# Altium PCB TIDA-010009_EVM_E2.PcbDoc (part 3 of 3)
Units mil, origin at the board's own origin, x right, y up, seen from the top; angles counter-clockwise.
Board outline 4485 x 3050 mil, 4 copper layers (Top Layer, Signal Layer 1, Signal Layer 2, Bottom Layer), stack 61.634 mil thick; 216 components, 95 nets, 514 pads, 224 vias.
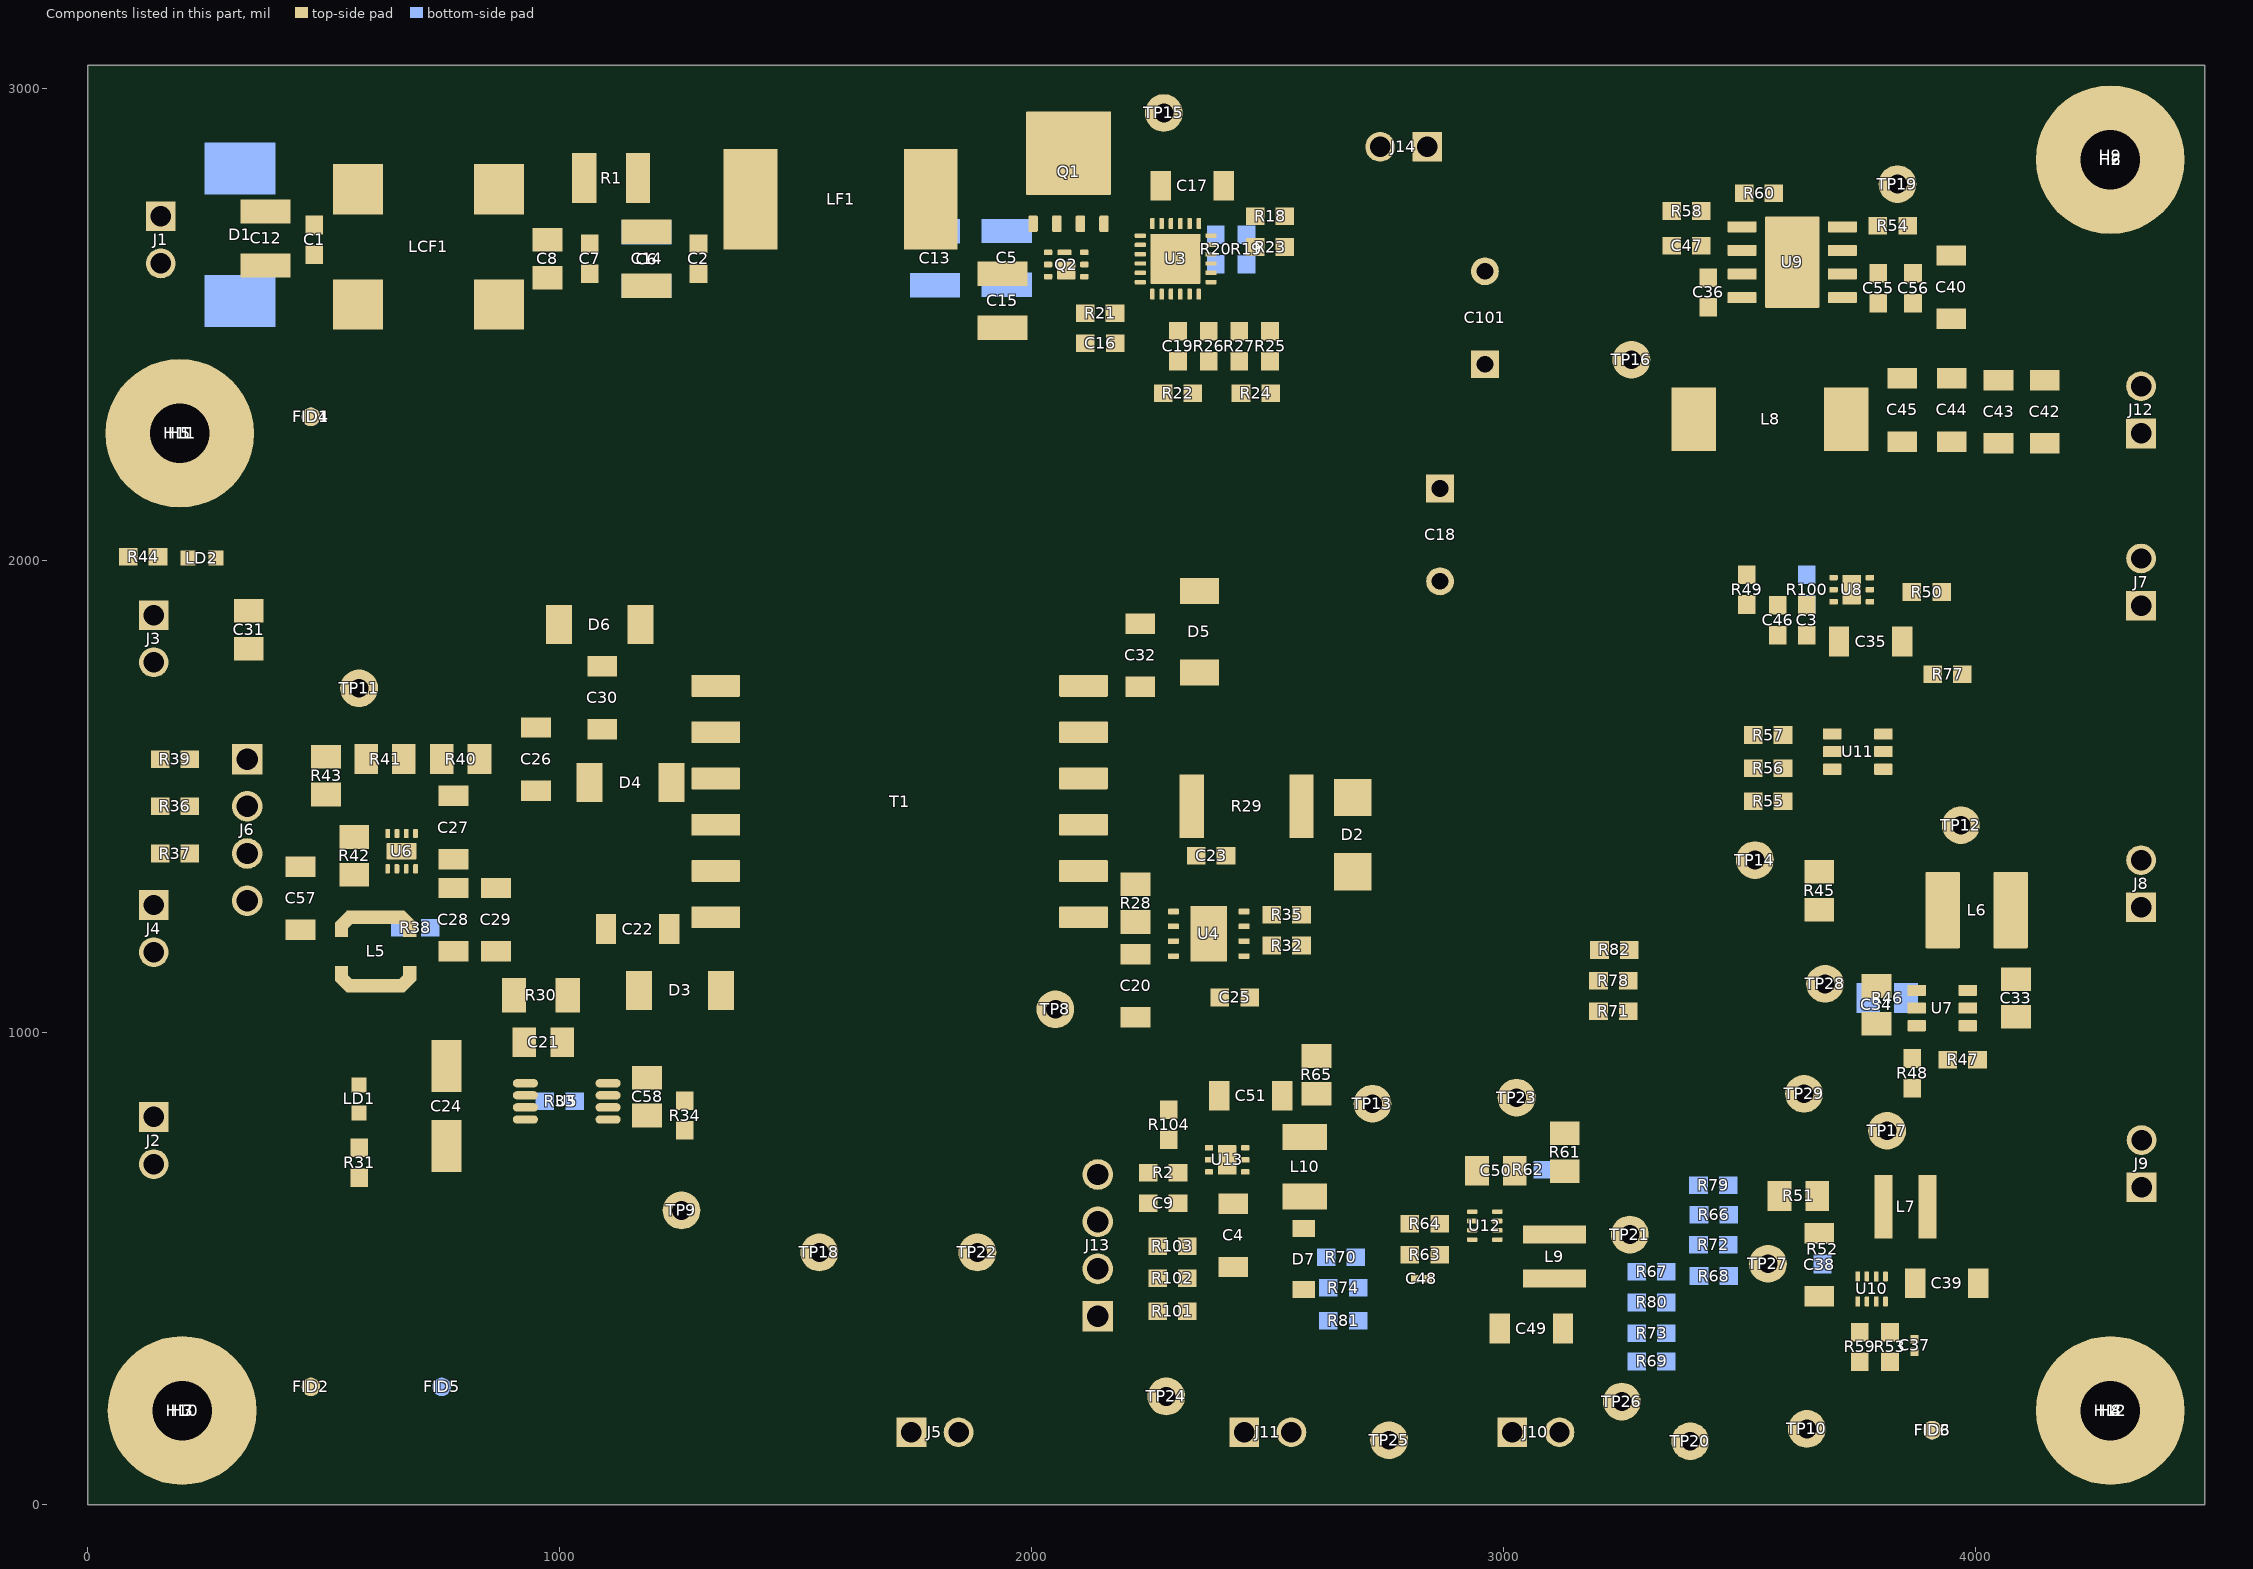
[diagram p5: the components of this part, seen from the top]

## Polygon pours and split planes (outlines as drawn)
GND on Top Layer "Top Layer-No Net" (solid, remove dead copper, pour order 122): 2535,1985 2535,1565 2160,1190 2160,90 2210,40 4415,40 4459.51,84.51 4459.51,2974.51 4465,2980 4425,3020 40,3020 20,3000 20,2510 165,2365 1780,2365 2155,2365
2.5V/1A on Top Layer "2.5V/1A_L01_P020" (solid, remove dead copper, pour order 20): 3038,500.49 3038,463 3090,411 3090,193 3078,181 3078,133.8 3114.3,97.5 3141.5,97.5 3174,130 3174,498.57 3168,504.57 3042.08,504.57
1.2V/1A on Top Layer "1.2V/1A_L01_P078" (solid, remove dead copper, pour order 78): 3977,438.88 3989.88,426 4114,426 4126,436 4252,562 4365,562 4392,589 4392,697 4385,704 4243.83,704 4078.83,539 4033,539 3988,584 3988,666.19 3934,720.19 3879.54,720.19 3873.5,714.16 3873.5,564.06 3884.56,553 3933.73,553 3977,509.73
EFUSE_OUT on Top Layer "Top Layer-No Net" (solid, remove dead copper, pour order 94): 2349.76,2929.76 2349.76,2993 2878,2993 2878,2729 2880,2727 2862.76,2709.76 2504.76,2709.76 2504,2710.53 2504,2848 2360,2848 2349.76,2858.24
GND on Top Layer "Top Layer-No Net" (solid, remove dead copper, pour order 124): 985,1400 1065,1400 1100,1435 1170,1435 1170,1417 1048,1295 985,1295
3.3V/2A on Top Layer "Top Layer-No Net" (solid, remove dead copper, pour order 108): 4290.32,1302 4158.32,1170 4134.82,1170 4121.29,1183.53 4121.29,1353.71 4108,1367 4040,1367 4018,1345 4018,1124.73 4065.73,1077 4233,1077 4382,1226 4395,1239 4395,1291 4384,1302
EFUSE_OUT on Top Layer "TOP_LAYER_EFUSE_OUT_P104" (solid, remove dead copper, pour order 116): 3375,2339.76 3248.04,2339.76 3198.56,2389.24 3198.56,2640.76 3120,2719.32 2937.55,2901.77 2937.55,2960 2904.55,2993 2823,2993 2790,2960 2790,2621.14 2724.08,2561 2638,2561 2579,2502 2579,2258 2624.43,2212.57 2625.84,1884.84 2246,1505 2188,1505 2160,1477 2046,1477 2031,1462 2031,1414 2042,1403 2269,1403 2320,1352 2365,1352 2370,1357 2370,1495 2529,1654 3136,1654 3375,1893 3375,2100
5V/3A on Top Layer "Top Layer-No Net" (solid, remove dead copper, pour order 118): 3459,755 3549.56,755 3608.56,696 3608.56,616.14 3603.42,611 3417,611 3249.71,778.29 3074.55,778.29 2804.47,778.29 2790,792.76 2790,901.29 2766.29,925 2640.84,925 2572,925 2563,934 2563,980.94 2662.06,1080 2830,1080 3065,1315 3065,1535 3363,1833 3363,2112 3380,2129 3572,2129 3587,2114 3587,2033 3572,2018 3507.94,2018 3471.3,1981.36 3471.3,1945.7 3492,1924 3571,1924 3585,1910 3585,1835 3550,1800 3550,1477.3 3580,1447.3 3723.3,1447.3 3779,1503 3779,1565 3786,1572 3825,1572 3834,1563 3834,1424 3725.49,1315.49 3561.49,1315.49 3559,1313 3353.97,1313 3285,1244.02 3285,1205 3256,1176 3176,1176 3140,1140 3140,1007.82 3206.18,1007.82
GND on Signal Layer 1 "SIGNAL_LAYER_1_GND_P084" (solid, remove dead copper, pour order 98): 0,0 0,3050 4475,3050 4485,3060 4485,0
EFUSE_OUT on Signal Layer 2 "EFUSE_OUT_L03_P084" (solid, remove dead copper, pour order 84): 3954,2682 3841,2571 3764,2571 3538,2345 3245,2345 3198,2345 3152,2391 3106,2391 3056,2341 3056,2228 3072.16,2212.16 3109.49,2174.82 3564.82,2174.82 3880,2490 4062,2490 4118,2546 4118,2667 4103,2682
GND on Signal Layer 2 "SIGNAL_LAYER_2_GND_P090" (solid, remove dead copper, pour order 106): 0,0 0,3045 4480,3045 4485,3050 4485,0
GND on Bottom Layer "Top Layer-No Net" (solid, remove dead copper, pour order 90): 4450,3019.74 4450,36 65,36 33,36 33,2973 33,3019.74

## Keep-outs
Keep-Out Layer:
  text ".Layer_Name" at 577,-858.49 h60

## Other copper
Top Layer:
  rectangle net 5V/3A: 3429,1835 3536,1925
  rectangle net 5V/3A: 3513,1885 3708,1924
  rectangle net NetD2_2: 2283.81,1249.19 2315,1294.65
  rectangle net GND: 2375,1249.94 2515,1265
  region net GND: 2967,574.53 2974.83,566.7 2996.83,566.7 2997.83,565.7 2997.83,531.7 3010,519.53 3010,461.87 3005.83,457.7 2911.26,457.7 2902.83,466.13 2902.83,533.7 2921.83,552.7 2921.83,583.7 2925.83,587.7 2948.83,587.7 2951.83,590.7 2951.83,638.7 2946.83,643.7 2935.96,643.7 2920.83,658.83 2920.83,735.7 2926.83,741.7 2973.77,741.7 2975.4,740.07 2975.4,648.26 2967,639.87
  region net VIN3: 3084.04,735.79 3035.53,735.79 3029.83,730.08 3029.83,644.67 3011.85,626.7 3011.85,617.53 3001.52,607.2 2976.33,607.2 2975.83,606.7 2975.83,597.7 2976.83,596.7 3013.7,596.7 3020.7,603.7 3127.83,603.7 3196.83,672.7 3196.83,729.7 3190.74,735.79
  region net 5V/3A: 3801,2300 3785.96,2315.04 3785.96,2368.04 3771.45,2382.54 3659.87,2382.55 3644.51,2367.19 3644.51,2248.51 3506.69,2110.69 3506.69,2054 3533.69,2027 3624,2027 3709,2112 3713,2113.54 4395,2113.54 4395,2300
  region net VIN2: 3635,581.91 3617,563.92 3482.81,563.92 3453,534.11 3453,492 3479,466 3579,466 3640.7,527.7 3726.12,527.7 3744.09,509.73 3753.26,509.73 3763.59,499.4 3763.59,474.2 3764.09,473.7 3773.09,473.7 3774.09,474.7 3774.09,513.7 3767.09,520.7 3767.09,625.7 3698.09,694.7 3641.09,694.7 3635,688.62
  region net GND: 3796.26,464.88 3804.09,472.7 3804.09,494.7 3805.09,495.7 3839.09,495.7 3864.09,520.7 3910.5,520.7 3933,498.2 3933,429.05 3904.66,400.7 3837.09,400.7 3818.09,419.7 3787.09,419.7 3783.09,423.7 3783.09,446.7 3780.09,449.7 3732.09,449.7 3727.09,444.7 3727.09,433.83 3711.96,418.7 3635.09,418.7 3629.09,424.7 3629.09,471.64 3630.72,473.27 3722.52,473.27 3730.92,464.88
  pour cut-out: 3552.21,2504 3640.62,2415.59 3640.62,2261.62 3516,2137 3405,2137 3386,2156 3386,2178 3403,2195 3449,2195 3489,2235 3489,2452 3541,2504
  region net VIN1: 3354,1125.21 3325.21,1154 3249.13,1154 3245,1158.13 3245,1195.39 3251.63,1202.02 3346.02,1202.02 3435,1291 3698.61,1291 3710.64,1278.98 3710.64,1191 3757.64,1144 3851,1144 3895,1100 3895,1079 3893,1077 3854,1077 3849,1072 3738,1072 3712,1046 3609,1046 3570.78,1006.78 3570.78,838.78 3522,790 3460.05,790 3354,896.05
  region net NetL6_1: 3890,1164 3962.88,1091.12 3962.88,1080 3964.84,1078.04 4001.54,1078.04 4003.5,1080 4003.5,1109.5 3993.79,1119.21 3993.79,1132 3968,1157.79 3968,1340.26 3967,1341.26 3893.15,1341.26 3890,1338.11
  region net NetR58_1: 3396,2720.5 3405,2711.5 3441.91,2711.5 3457.46,2695.94 3534.21,2695.94 3535,2696.73 3535,2755.64 3530.64,2760 3530.64,2797.36 3526,2802 3423,2802 3396,2775
  region net NetC36_2: 3367,2496 3405,2534 3405,2555 3412,2562 3460,2562 3472,2574 3530.8,2574 3535,2569.8 3535,2520.91 3482,2467.91 3482,2248 3444,2210 3292,2210 3222,2280 3222,2469 3249,2496
  region net EFUSE_OUT: 3687,2597 3687,2618 3689,2620 3752.89,2620 3762.81,2629.92 3833.92,2629.92 3877.26,2673.26 4063.74,2673.26 4081,2656 4081,2595 4064.41,2578.41 3896.05,2578.41 3888,2586.46 3760.55,2586.46 3756.2,2590.81 3693.19,2590.81
  region net GND: 2026,2420 2009.5,2436.5 2009.5,2499.5 1989,2520 1885.76,2520 1846,2559.76 1846,2590.55 1841.54,2590.55 1820,2612.09 1781.09,2612.09 1752,2583 1752,2523 1800,2475 1900,2375 2230,2375 2230,2485 2150,2485 2150,2420
  pour cut-out: 0,1700 485.97,1700 485.97,1804.75 675.97,1804.75 675.97,1670 2284.52,1670 2284.52,1896.21 2050.97,2129.75 1.44,2129.75
  pour cut-out: 490,815 485,815 492.5,822.5 497.5,822.5
  pour cut-out: 0,610 495,610 590,515 1430,515 1570,655 1570,1340 1490,1420 985,1420 985,1170 0,1170
  region net EFUSE_OUT: 2369.76,2664.76 2369.76,2704.76 2349.76,2704.76 2349.76,2734.76 2424.76,2734.76 2414.76,2724.76 2414.76,2674.76 2404.76,2664.76
  region net NetR49_2: 3496.32,1954 3707,1954 3707,1979 3667,1979 3496.32,1979
  region net GND: 408,1341.95 420,1329.95 482.66,1329.95 485,1332.29 485,1359.5 495.5,1370 700,1370 737.71,1332.29 740.47,1332.29 740.47,1295 1020,1295 1020,1400 630,1400 620,1400 605,1415 605,1530 408,1530
  region net VDD_EXTERNAL: 84.5,1222 65,1241.5 65,1585.7 86.5,1607.2 168.31,1607.2 175.51,1600 175.51,1405.49 179,1402 179,1320.04 192.04,1307 208,1307 285.21,1229.79 286,1229.79 498.5,1229.79 498.5,1177.75 721.5,1177.75 721.5,1203.57 903.37,1203.57 904.37,1204.57 905,1145 905,1140 760,1140 684,1064 516,1064 470,1110 302.5,1110 249,1110 195,1164 195,1199 172,1222
  region net 12V/250mA: 1090,1600 800,1600 800,1530 735,1530 670,1465 670,1445 671.12,1443.88 1090,1443.88
  region net NetQ1_5: 2159.76,2764 2149,2774.76 1985.24,2774.76 1979,2781 1979,2952 1987,2960 2162.65,2960 2199.76,2922.89 2199.76,2789.76 2255.55,2733.98 2255.55,2704.76 2239.76,2704.76 2239.76,2669.76 2239.29,2669.29 2218.45,2669.29 2184.52,2703.21 2184.52,2724.59 2159.76,2749.35
  region net 24V_INPUT: 80,2700 626,2700 626,2910 80,2910
  region net NetC1_1: 80,2660 628,2660 628,2480 80,2480
  region net NetC7_2: 806,2660 806,2880 1094,2880 1094,2660
  region net NetC2_2: 1124,2660 1463,2660 1463,2875 1124,2875
  region net NetC5_1: 1856,2659.39 1878,2637.39 1878,2580.76 1900.76,2558 1964,2558 1981,2541 2013.76,2541 2048,2506.76 2048,2455 2061.42,2441.57 2133.57,2441.58 2137,2445 2137,2555 2123,2569 2022.18,2569 1996,2595.18 1996,2620 2023,2647 2079,2647 2115,2683 2121.73,2683 2126,2687.27 2126,2735.5 2122.02,2739.48 1932,2739.48 1932,2831 1880.5,2882.5 1724,2882.5 1724,2659.39
  region net GND: 802,2632.5 1847,2632.5 1847,2452.5 802,2452.5
  region net VDD_ENCODER1: 3817,1884 3797,1904 3797,1918 3791,1924 3770.23,1924 3767.16,1920.93 3767.16,1908.84 3817,1859 3817,1794 4402,1794 4402,1949 4217,1949 4152,1884
  region net GND: 3717,1974 3717,1873.88 3707.12,1864 3557,1864 3557,1799 3661,1695 3757,1695 3757,1974
  region net VDD_ENCODER2: 2515.27,475 2601,475 2603.98,472.02 2603.98,421.37 2564.07,381.46 2540.73,381.46 2485,325.73 2485,120 2220.73,120 2220.73,300 2309,300 2309,565.95 2315.05,572 2390.07,572 2419.07,543 2458.94,543 2483.01,518.92 2483.01,506.68
  region net NetD2_2: 2336,1280 2324,1280 2318,1274 2318,1252.19 2315,1249.19 2282.81,1249.19 2245,1287 2058,1287 2055,1290 2055,1374.75 2245.25,1374.75 2283.96,1336.04 2456,1335.17 2464.17,1335.17 2512,1383 2720,1383 2720,1280
  region net NetD5_2: 2055,1605 2204,1605 2239.96,1605 2240.21,1675 2055,1675
  region net NetD6_1: 1383,1710 1383,1910 1140,1910 1140,1825 1255,1710
  region net NetD4_2: 1390,1580 1390,1510 1295,1510 1265,1480 1201.85,1480 1200,1481.85 1200,1580
  region net 24V/100mA: 950,887.29 950,1110.43 954.57,1115 860.49,1115 741.49,996 131,996 78,943 78,796 95,779 450,779 541,870 855,870 872.29,887.29 956.04,887.29
  region net NetC22_1: 1226.41,887.29 1347.29,887.29 1375,915 1375,990 1335,1030 1114,1030 1080,996 1080,887.29
  region net NetD3_2: 1390,1280 1280,1280 1280,1045 1390,1045
  region net GND1: 1490,820 1490,640 1405,555 625,555 520.97,659.03 520.97,715 590,715 725,850 966,850 966,775 1127,775 1172,820
  pour cut-out: 0,2050 741,2050 741,2600 0,2600
  region net EFUSE_OUT: 2349.76,2929.76 2639.76,2929.76 2639.76,2709.76 2504.76,2709.76 2504.76,2799.76 2439.76,2799.76 2439.76,2749.76 2414.76,2724.76 2349.76,2724.76
  region net -12V/100mA: 1125,1750 1125,1905 970,1905 970,1750
  region net GND: 1170,1653.5 1170,1418.5 1115,1418.5 1115,1653.5
  region net NetL5_1: 670,1330 685,1330 690,1325 690,1230 655,1230 655,1315
  region net GND2: 2000,1710 2262,1710 2262,1800 2000,1800
  region net GND1: 1278.96,1320 1255,1296.04 1255,1186.06 1195,1186.06 1195,1320 1260,1385 1385,1385 1385,1320
  region net NetC22_1: 1200,1140 1130,1210 1130,1259.37 1070,1259.37 1070,1175 1135,1110 1135,995 1200,995
  region net GND1: 1355,1320 1430,1320 1445,1305 1445,1050 1445,640 1490,640 1530,680 1530,1335 1475,1390 1355,1390
  region net GND1: 95.32,751.76 545,751.76 545,658.24 94.68,658.24
  pour cut-out: 3687.15,1882.27 3711.63,1882.27 3693.36,1864 3676.61,1864 3676,1863.39 3676,1873 3677.41,1873 3687.26,1882.86
  pour cut-out: 3617.49,1858.51 3783.49,1858.51 3792,1850 3791.51,1849.51 3791.51,1792.49 3815.49,1768.51 3863.82,1768.51 3863.82,1761.67 3775.7,1673.56 3775.7,1598.98 3775.98,1598.71 3775.98,1529.09 3733.19,1486.3 3699.22,1486.3 3699.22,1489.19 3697.44,1490.97 3727.01,1520.55 3727.01,1566.3 3739.86,1579.15 3718,1601 3718,1663 3664,1663 3663,1662 3588,1662 3583,1667 3583,1671.3 3575.49,1678.81 3575.49,1816.51
  pour cut-out: 3758.29,1884.5 3773.71,1884.5 3791.51,1866.7 3791.51,1857.02 3788.74,1854.26 3761.74,1854.26 3757,1859 3757,1883.21
  region net NetQ1_4: 2026,2634 2122,2634 2122,2590.18 2120.82,2589 2030,2589 2023,2596 2024,2597 2024,2632
  region net VIN4: 2443.27,750.89 2521.44,750.89 2545.44,726.89 2623.61,726.89 2702.41,805.69 2734.69,805.69 2765,836 2765,865.66 2731.66,899 2502,899 2499,896 2499,819.16 2443.27,763.43
  region net NetD7_2: 2443.27,695.71 2448.98,690 2492.31,690 2529,653.31 2529,618 2548,599 2548,566.7 2551,563.7 2599.7,563.7 2628,592 2628,683 2624,687 2537,687 2512,712 2444.92,712 2443.27,710.35
  pour cut-out: 2962.78,2961.33 2962.78,3024.64 2952.42,3035 2926.12,3035 2901.98,3010.86 2921.11,2991.72 2921.11,2985 2944.79,2961.33
  text ".Layer_Name" at 577,-858.49 h60
Signal Layer 1:
  region net GND1: 95.32,751.76 545,751.76 545,658.24 94.68,658.24
  region net GND1: 1355,1320 1430,1320 1445,1305 1445,1050 1445,640 1490,640 1530,680 1530,1335 1475,1390 1355,1390
  region net GND1: 1278.96,1320 1255,1296.04 1255,1186.06 1195,1186.06 1195,1320 1260,1385 1385,1385 1385,1320
  region net GND1: 1490,820 1490,640 1405,555 625,555 520.97,659.03 520.97,715 590,715 725,850 966,850 966,775 1127,775 1172,820
  pour cut-out: 0,610 495,610 590,515 1430,515 1570,655 1570,1340 1490,1420 985,1420 985,1170 0,1170
  pour cut-out: 2765,1885 2765,1565 1970,1565 1970,1885
  pour cut-out: -0.97,1700.25 485,1700.25 485,1805 675,1805 675,1670 2283.55,1670 2283.55,1896.45 2050,2130 0.47,2130
  pour cut-out: 10,2430 890,2430 890,2980 10,2980
  text ".layer_Name" at 663,-862 h60
Signal Layer 2:
  region net 24V/100mA: 950,887.29 950,1110.43 954.57,1115 860.49,1115 741.49,996 131,996 78,943 78,796 95,779 450,779 541,870 855,870 872.29,887.29 956.04,887.29
  region net GND1: 95.32,751.76 545,751.76 545,658.24 94.68,658.24
  region net GND1: 1355,1320 1430,1320 1445,1305 1445,1050 1445,640 1490,640 1530,680 1530,1335 1475,1390 1355,1390
  region net GND1: 1278.96,1320 1255,1296.04 1255,1186.06 1195,1186.06 1195,1320 1260,1385 1385,1385 1385,1320
  region net GND1: 1490,820 1490,640 1405,555 625,555 520.97,659.03 520.97,715 590,715 725,850 966,850 966,775 1127,775 1172,820
  pour cut-out: 0,610 495,610 590,515 1430,515 1570,655 1570,1340 1490,1420 985,1420 985,1170 0,1170
  pour cut-out: 2765,1885 2765,1565 1970,1565 1970,1885
  pour cut-out: 0,1700 485.97,1700 485.97,1804.75 675.97,1804.75 675.97,1670 2284.52,1670 2284.52,1896.21 2050.97,2129.75 1.44,2129.75
  pour cut-out: 10,2430 890,2430 890,2980 10,2980
  text ".layer_Name" at 662,-849 h60
Bottom Layer:
  rectangle net NetQ1_5: 1979,2774.78 2168.72,2955
  region net NetC1_1: 80,2660 483,2660 483,2480 80,2480
  region net GND: 2967,574.53 2974.83,566.7 2996.83,566.7 2997.83,565.7 2997.83,531.7 3010,519.53 3010,474.7 2958.14,474.7 2902.83,530.01 2902.83,533.7 2921.83,552.7 2921.83,583.7 2925.83,587.7 2948.83,587.7 2951.83,590.7 2951.83,638.7 2946.83,643.7 2935.96,643.7 2920.83,658.83 2920.83,735.7 2945.24,735.7 2975.4,705.54 2975.4,648.26 2967,639.87
  region net GND: 3839.09,495.7 3868.44,466.36 3868.44,428.36 3840.78,400.7 3837.09,400.7 3818.09,419.7 3787.09,419.7 3783.09,423.7 3783.09,446.7 3780.09,449.7 3732.09,449.7 3727.09,444.7 3727.09,433.83 3711.96,418.7 3635.09,418.7 3635.09,443.11 3665.25,473.27 3722.52,473.27 3730.92,464.88 3796.26,464.88 3804.09,472.7 3804.09,494.7 3805.09,495.7
  region net VIN1: 3788,1036 3805,1053 3805,1129.15 3789.26,1144 3757.64,1144 3710.64,1191 3710.64,1278.98 3698.61,1291 3435,1291 3366.4,1222.4 3354,1208.79 3354,896.05 3460.05,790 3522,790 3570.78,838.78 3570.78,1006.78 3599.25,1036
  region net NetC2_2: 1112.47,2739.96 1112.47,2682.53 1127,2668 1299.76,2668 1312,2680.24 1312,2793.5 1293.5,2812 1235,2812 1172.28,2749.28 1121.78,2749.28
  region net 24V_INPUT: 105,2695 105,2881 161,2937 445.02,2937 484,2898.02 484,2708 471,2695
  region net NetC5_1: 1738.25,2815.62 1766.55,2843.92 1892.08,2843.92 1919,2817 1919,2778.51 1963.51,2733.56 1999.44,2733.56 2010,2723 2010,2679 2001,2670 1740.48,2670 1738.25,2672.24
  pour cut-out: 0,610 495,610 590,515 1430,515 1570,655 1570,1340 1490,1420 985,1420 985,1119 0,1119
  pour cut-out: 0,1700 485.97,1700 485.97,1804.75 675.97,1804.75 675.97,1670 2284.52,1670 2284.52,1896.21 2050.97,2129.75 1.44,2129.75
  pour cut-out: 2765,1885 2765,1565 1970,1565 1970,1885
  region net EFUSE_OUT: 2349.76,2719.77 2434.76,2719.77 2434.76,2799.76 2504.76,2799.76 2504.76,2743.32 2629.76,2743.32 2629.76,2849.76 2349.76,2849.76
  pour cut-out: 0,2050 813,2050 813,2600 0,2600
  region net EFUSE_OUT: 2349.76,2724.76 2441.52,2724.76 2455.22,2711.06 2473,2711.06 2473,2672.46 2473.46,2672 2471.46,2670 2360,2670 2349.76,2680.24
  text ".Layer_Name" at 577,-858.49 h60

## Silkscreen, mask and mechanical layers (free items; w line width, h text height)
Top Overlay:
  region: 1471,2318 1171,2318 1171,2218 1471,2218
  lines w6: 2234,747 2234,827 2208,853 2180,853 2181,853 ; 2249,371 2249,349 2266,332 2359,332 ; 2345.87,340 2347,338.87 2347,320 ; 2543,2521 2632,2521 2645,2508 ; 3005,625 3095,625 3100,630 ; 3688,2032 3699,2032 3727,2004 3727,1999 ; 2181,853 2192,864 2192,842 2181,853 ; 2347,320 2344,320 2344,347 2359,332 ; 2347,320 2359,332 ; 2347,320 2349,322 2349,336 2353,332 2359,332
  text "+" at 2920,2895 h72.83
  text "+24V" at 30,2820 h40
  text "+5V" at 4325,2150 h40
  text "+" at 15,1956.57 h40
  text "+5V" at 300,1950 h40
  text "+" at 4380,1765 h72.83
  text "+" at 40,1345 h40
  text "+3.3V" at 4285,1137.84 h40
  text "+24V" at 10,900 h40
  text "+1.2V" at 4300,547.06 h40
  text "+" at 2312.27,70 h72.83
  text "-12V" at 1658.94,30 h40 r90
  text "+2.5V" at 3205,20 h40
  text ".Layer_Name" at 577,-858.49 h60
Bottom Overlay:
  text ".Layer_Name" at 577,-858.49 h60
Top Paste:
  text ".Layer_Name" at 577,-858.49 h60
Bottom Paste:
  text ".Layer_Name" at 577,-858.49 h60
Top Solder:
  text ".Layer_Name" at 577,-858.49 h60
  text ".Layer_Name" at 577,-858.49 h60
Bottom Solder:
  text ".Layer_Name" at 577,-858.49 h60
Drill Guide:
  text ".Layer_Name" at 577,-858.49 h60
M1 Board Outline:
  the board outline again, w10
  text "'.Layer_Name'" at 560,-855 h60
M2 Board Dimensions:
  rectangle: 0,-275 125,-150
  rectangle: 125,-400 500,-275
  lines w7: 0,-275 1000,-275 ; 125,-400 125,-150 ; 250,-400 250,-150 ; 500,-400 500,-150 ; 750,-400 750,-150 ; 0,-400 1000,-400 1000,-150 0,-150 0,-400
M3 3D STEP Top:
  text ".Layer_Name" at 577,-858.49 h60
M4 3D STEP Bottom:
  text ".Layer_Name" at 577,-858.49 h60
M5 Assembly Top:
  region: 1383,1695.67 1383,1922.91
  lines w10: -292,-930.17 6308,-930.17 ; -292,-726.83 6310,-726.83 ; -292,-523.5 -292,-1133.5 3713,-1133.5 6310,-1133.5 6310,-523.5 -291.5,-523.5 -291.5,-1133.5 1284,-1133.5 ; 2173,-1133.5 2173,-523.5 ; 3440,-726.83 3440,-523.5 ; 4280,-726.83 4280,-523.5 ; 4902,-1140 4902,-937.17
  text "COMPONENTS MARKED 'DNP' SHOULD NOT BE POPULATED." at 1153.5,-318.5 h60
  text "ASSEMBLY VARIANT:" at 1153,-434 h60
  text ".VariantName" at 2189,-434 h60
  text "PCB VIEWED FROM TOP SIDE" at -228.5,-655.67 h60
  text "BOARD #:" at 2248,-655.67 h60
  text ".PRJ_Number" at 2793.5,-655.67 h60
  text "REV:" at 3638,-655.67 h60
  text ".PCB_Rev" at 3929.5,-655.67 h60
  text "SVN REV:" at 4476,-655.67 h60
  text ".VersionControl_RevNumber" at 4982,-655.67 h60
  text "TID #:" at 2248,-859 h60
  text ".TID" at 2793.5,-859 h60
  text ".layer_Name" at 585,-880 h60
  text "PLOT NAME =" at -228.5,-1064.34 h60
  text ".plot_File_Name" at 577,-1064.34 h60
  text "GENERATED    :" at 2250,-1064.34 h60
  text ".Print_Date" at 3119.5,-1064.34 h60
  text ".Print_Time" at 3848.5,-1064.34 h60
  text "TEXAS INSTRUMENTS" at 5113,-1064.34 h60
M6 Assembly Bottom:
  lines w10: -292.5,-727.33 6309.5,-727.33 ; -290.5,-930.67 6309.5,-930.67 ; 1115.5,-1140.5 1115.5,-937.67 ; 1737.5,-727.33 1737.5,-524 ; 2577.5,-727.33 2577.5,-524 ; 3844.5,-1134 3844.5,-524 ; 4733.5,-1134 6309,-1134 6309,-524 -292.5,-524 -292.5,-1134 2304.5,-1134 6309.5,-1134 6309.5,-524
  text "COMPONENTS MARKED 'DNP' SHOULD NOT BE POPULATED." at 6102,-318 h60
  text ".VariantName" at 5058,-434 h60
  text "ASSEMBLY VARIANT:" at 6097,-434 h60
  text ".VersionControl_RevNumber" at 1035.5,-656.17 h60
  text "SVN REV:" at 1541.5,-656.17 h60
  text ".PCB_Rev" at 2088,-656.17 h60
  text "REV:" at 2379.5,-656.17 h60
  text ".PRJ_Number" at 3224,-656.17 h60
  text "BOARD #:" at 3769.5,-656.17 h60
  text "PCB VIEWED FROM BOTTOM SIDE" at 6246,-656.17 h60
  text ".layer_Name" at 5192,-854 h60
  text ".TID" at 3224,-859.5 h60
  text "TID #:" at 3769.5,-859.5 h60
  text "TEXAS INSTRUMENTS" at 904.5,-1064.84 h60
  text ".Print_Time" at 2169,-1064.84 h60
  text ".Print_Date" at 2898,-1064.84 h60
  text "GENERATED    :" at 3767.5,-1064.84 h60
  text ".plot_File_Name" at 5440.5,-1064.84 h60
  text "PLOT NAME =" at 6246,-1064.84 h60
M9 Title Sheet:
  drawing of 57 lines, arcs and shapes, not listed
  text "1" at 739.84,8036.5 h70
  text "2" at 3235.5,8036.5 h70
  text "3" at 5724.84,8036.5 h70
  text "4" at 8231.51,8036.5 h70
  text "5" at 10730.5,8036.5 h70
  text "6" at 13235.5,8036.5 h70
  text "A" at -416.5,6893.5 h70
  text "A" at 14383.5,6893.5 h70
  text "B" at -416.5,4513.5 h70
  text "B" at 14383.5,4513.5 h70
  text "C" at -416.5,2138.5 h70
  text "C" at 14383.5,2138.5 h70
  text "PROJECT TITLE:" at 11343.5,277.5 h45
  text ".PRJ_Title" at 11393.5,144.17 h70
  text "DESIGNED FOR:" at 11343.5,-23.5 h45
  text ".PRJ_Customer" at 11393.5,-163.5 h70
  text "D" at -416.5,-231.5 h70
  text "D" at 14383.5,-231.5 h70
  text "FILE NAME:" at 11343.5,-323.5 h45
  text ".PCB_File_Name_No_Path" at 11393.5,-443.5 h70
  text "Texas Instruments (TI) and/or its licensors do not warrant the accuracy or completeness of this specification" at 6374,-605.34 h45
  text "ENGINEER:" at 11343.5,-613.5 h45
  text "LAYOUT BY:" at 12848.5,-613.5 h45
  text "or any information contained therein. TI and/or its licensors do not warrant that this design will meet" at 6329.01,-718 h45
  text ".PRJ_Engineer" at 11393.5,-768.49 h70
  text ".PCB_Layout" at 12899,-768.49 h70
  text "the specifications, will be suitable for your application or fit for any particular purpose, or will operate in" at 6329.01,-830.67 h45
  text "ALTIUM DESIGNER VERSION:" at 12848.5,-923.5 h45
  text "an implementation. TI and/or its licensors do not warrant that the design is production worthy. You should" at 6329.01,-943.33 h45
  text "completely validate and test your design implementation to confirm the system functionality for your application." at 6374,-1056 h45
  text ".print_Scale" at 11393.5,-1056.83 h70
  text ".Application_BuildNumber" at 12899,-1056.83 h70
  text "1" at 739.84,-1263.5 h70
  text "2" at 3235.5,-1263.5 h70
  text "3" at 5724.84,-1263.5 h70
  text "4" at 8231.51,-1263.5 h70
  text "5" at 10730.5,-1263.5 h70
  text "6" at 13235.5,-1263.5 h70
M10 Fab Notes:
  drawing of 189 lines, arcs and shapes, not listed
  text "DESIGN INFORMATION" at 12382.02,6356.17 h60
  text "MIN. TRACK WIDTH:" at 11737.46,6224.05 h60
  text "8" at 12833.7,6224.05 h60
  text "MIL" at 12988.46,6224.05 h60
  text "6" at 12843,6110 h60
  text "MIN. CLEARANCE:" at 11737.46,6099.92 h60
  text "MIL" at 12988.46,6099.92 h60
  text "MIN. VIA PAD SIZE:" at 11737.46,5975.8 h60
  text "MIL" at 12988.46,5975.8 h60
  text "19.68" at 12683,5975 h60
  text "0.05mm (2MIL)" at 12432.46,5845.9 h60
  text "MINIMUM ANNULAR RING" at 11408.23,5837.67 h60
  text "EXTERNAL" at 13140.46,5837.67 h60
  text "PER" at 11608.23,5727.55 h60
  text "IPC-D-275 CLASS 2 LEVEL C" at 11828.23,5727.54 h60
  text "MIL, HOLES" at 13316.46,5627.07 h60
  text "+/-" at 12924,5618.48 h60
  text "+/-" at 13778,5618.48 h60
  text "REGISTRATION TOLERANCES:" at 11408.23,5617.42 h60
  text "METAL" at 12608,5617.42 h60
  text "5" at 13184.2,5617.42 h60
  text "3" at 14017.2,5617.42 h60
  text "MIL" at 14133.46,5617.42 h60
  text "HOLE SIZE TOLERANCE (UNLESS OTHERWISE SPECIFIED):" at 11408.23,5519.1 h60
  text "+/-" at 13778,5516.23 h60
  text "3" at 14017.2,5515.17 h60
  text "MIL" at 14133.46,5515.17 h60
  text "MATERIAL:" at 11333.46,5377.52 h60
  text "FR-4 High Tg" at 12319.9,5249 h60
  text "X" at 12175.46,5241.01 h60
  text "FR-408" at 11754.46,5236.49 h60
  text "OTHER" at 13242.46,5236.49 h60
  text "62 MIL (1.6mm) +/-10%" at 12074.56,5093.46 h60
  text "X" at 11954.46,5091.01 h60
  text "THICKNESS:" at 11408.23,5085.24 h60
  text "OTHER" at 13359.46,5085.24 h60
  text "TOLERANCE:" at 11408.23,4946.92 h60
  text "X" at 12256.46,4946.92 h60
  text "ANSI IPC-6012 TYPE 3 CLASS 2" at 12434.48,4946.92 h60
  text "OTHER +/-" at 12434.46,4802.73 h60
  text "BOW & TWIST:" at 11408.23,4657.54 h60
  text "X" at 12256.46,4657.54 h60
  text "ANSI IPC-6012 TYPE 3 CLASS 2" at 12434.48,4657.54 h60
  text "OTHER +/-" at 12434.46,4510.85 h60
  text "DRILLING:" at 11333.46,4380.23 h60
  text "NC_DRILL FILES" at 13094.46,4275.04 h60
  text "REFERENCE:" at 11408.23,4271.1 h60
  text "X" at 12065.46,4271.01 h60
  text "AS SHOWN" at 12243.46,4271.1 h60
  text "X" at 12966.46,4271.1 h60
  text "OTHER" at 13392.46,4128.85 h60
  text "PTH COPPER THICKNESS:" at 11407.91,4125.32 h60
  text "X" at 12547.14,4125.32 h60
  text "20-30 um" at 12675.14,4125.32 h60
  text "BOARD FINISH:" at 11333.46,3977.73 h60
  text "SILKSCREEN:" at 11488.68,3867.6 h60
  text "X" at 12446.46,3867.6 h60
  text "TOP" at 12563.46,3867.6 h60
  text "X" at 12956.46,3867.6 h60
  text "BOTTOM" at 13074.46,3867.6 h60
  text "SILKSCREEN COLOR:" at 11488.68,3712.41 h60
  text "X" at 12445.46,3712.41 h60
  text "WHITE" at 12563.46,3712.41 h60
  text "OTHER" at 13074.46,3712.41 h60
  text "X" at 12576.46,3568.96 h60
  text "GREEN" at 12694.46,3568.96 h60
  text "OTHER" at 13312.46,3568.96 h60
  text "SOLDER RESIST COLOR:" at 11488.68,3562.1 h60
  text "MATTE" at 12694.46,3414.71 h60
  text "SEMI-GLOSS" at 13312,3414.07 h60
  text "IMMERSION GOLD (ENIG)" at 12394.46,3241.94 h60
  text "ENEPIG" at 13732,3234.72 h60
  text "SURFACE FINISH:" at 11333.46,3233.72 h60
  text "X" at 12216.46,3233.72 h60
  text "IMM. TIN/SILVER OR EQUIV" at 11663,3096.4 h60
  text "OTHER" at 13094.46,3092.47 h60
  text "ARRAY/PANEL:" at 11333.46,2937.09 h60
  text "CUT AND TRIM PER M1 BOARD OUTLINE" at 12394.46,2928.87 h60
  text "X" at 12225,2925 h60
  text "N.C. ROUTE" at 12394.46,2792.9 h60
  text "V. SCORE" at 13260.46,2792.9 h60
  text "CERTIFICATION:" at 11333.46,2663.77 h60
  text "MATERIALS AND WORKMANSHIP FOR ALL PCBS" at 12058.46,2663.77 h60
  text "TO MEET OR EXCEED THE REQUIREMENTS OF:" at 12058.46,2569.71 h60
  text "X" at 11695.97,2441.08 h60
  text "ANSI IPC-A-600F CLASS ->" at 11823.96,2441.08 h60
  text "X" at 13471.97,2441.08 h60
  text "2" at 13581.96,2441.08 h60
  text "1" at 13266.96,2439.58 h60
  text "3" at 13935.96,2439.58 h60
  text "X" at 12507.97,2293.39 h60
  text "RoHS" at 12635.96,2293.39 h60
  text "OTHER" at 13280.36,2293.39 h60
  text "PER ORDER" at 13677.42,2293.39 h60
  text "ALL BOARDS MUST MEET OR EXCEED UL94-V0 REQUIREMENTS." at 11361,2139.57 h60
  text "PCB MUST BEAR THE UL94V-0 UL REGISTERED MATERIAL ID NUMBER" at 11361,2023.5 h60
  text "ADDITIONAL REQUIREMENTS:" at 11333.46,1854.08 h60
  text "MICROSECTION:" at 11408.23,1746.95 h60
  text "YES" at 12313.96,1746.95 h60
  text "REQUIRED" at 13175.46,1602.62 h60
  text "BARE BOARD ELEC. TEST:" at 11408.23,1599.76 h60
  text "NONE" at 12713.96,1599.76 h60
  text "X" at 13057.46,1599.76 h60
  text "PER ORDER" at 13767.46,1599.76 h60
  text "XX MIL VIAS REQUIRE NON-CONDUCTIVE FILL AND PLANARIZE" at 11576.38,1394.82 h59
  text "XX MIL VIAS REQUIRE CONDUCTIVE FILL AND PLANARIZE" at 11584.38,1290.84 h60
  text "OUTER XX MIL TRACES REQUIRE 50 OHM SINGLE-ENDED IMPEDANCE" at 11583.39,1127.46 h58
M11 Gerber Information:
  lines w10: -292,-930.17 6308,-930.17 ; -292,-726.83 6310,-726.83 ; -292,-523.5 -292,-1133.5 3713,-1133.5 6310,-1133.5 6310,-523.5 -291.5,-523.5 -291.5,-1133.5 1284,-1133.5 ; 2173,-1133.5 2173,-523.5 ; 3440,-726.83 3440,-523.5 ; 4280,-726.83 4280,-523.5 ; 4902,-1140 4902,-937.17
  text "ALL ARTWORK VIEWED FROM TOP SIDE" at -228.5,-655.67 h60
  text "BOARD #:" at 2248,-655.67 h60
  text ".PRJ_Number" at 2793.5,-655.67 h60
  text "REV:" at 3638,-655.67 h60
  text ".PCB_Rev" at 3929.5,-655.67 h60
  text "SVN REV:" at 4476,-655.67 h60
  text ".VersionControl_RevNumber" at 4982,-655.67 h60
  text "LAYER NAME =" at -228.5,-858.49 h60
  text "TID #:" at 2248,-859 h60
  text ".TID" at 2793.5,-859 h60
  text "PLOT NAME =" at -228.5,-1064.34 h60
  text ".plot_File_Name" at 577,-1064.34 h60
  text "GENERATED    :" at 2250,-1064.34 h60
  text ".Print_Date" at 3119.5,-1064.34 h60
  text ".Print_Time" at 3848.5,-1064.34 h60
  text "TEXAS INSTRUMENTS" at 5113,-1064.34 h60
M12 Stackup:
  drawing of 295 lines, arcs and shapes, not listed
  text "Layer" at 9797.84,7762.5 h60
  text "Name" at 10207.76,7762.5 h60
  text "Material" at 11147.5,7762.5 h60
  text "Thickness" at 12007.26,7762.5 h60
  text "Constant" at 12657.1,7762.5 h60
  text "Board Layer Stack" at 13226.96,7762.5 h60
  text "1" at 9797.84,7642.5 h60
  text "Top Overlay" at 10207.76,7642.5 h60
  text "2" at 9797.84,7522.5 h60
  text "Top Solder" at 10207.76,7522.5 h60
  text "Solder Resist" at 11147.5,7522.5 h60
  text "0.40mil" at 12007.26,7522.5 h60
  text "3.5" at 12657.1,7522.5 h60
  text "3" at 9797.84,7402.5 h60
  text "Top Layer" at 10207.76,7402.5 h60
  text "Copper" at 11147.5,7402.5 h60
  text "1.40mil" at 12007.26,7402.5 h60
  text "4" at 9797.84,7282.5 h60
  text "Dielectric 2" at 10207.76,7282.5 h60
  text "FR-4 High Tg" at 11147.5,7282.5 h60
  text "14.00mil" at 12007.26,7282.5 h60
  text "4.2" at 12657.1,7282.5 h60
  text "5" at 9797.84,7162.5 h60
  text "Signal Layer 1" at 10207.76,7162.5 h60
  text "Copper" at 11147.5,7162.5 h60
  text "1.42mil" at 12007.26,7162.5 h60
  text "6" at 9797.84,7042.5 h60
  text "Dielectric1" at 10207.76,7042.5 h60
  text "FR-4 High Tg" at 11147.5,7042.5 h60
  text "28.00mil" at 12007.26,7042.5 h60
  text "4.8" at 12657.1,7042.5 h60
  text "7" at 9797.84,6922.5 h60
  text "Signal Layer 2" at 10207.76,6922.5 h60
  text "Copper" at 11147.5,6922.5 h60
  text "1.42mil" at 12007.26,6922.5 h60
  text "8" at 9797.84,6802.5 h60
  text "Dielectric 3" at 10207.76,6802.5 h60
  text "FR-4 High Tg" at 11147.5,6802.5 h60
  text "14.00mil" at 12007.26,6802.5 h60
  text "4.2" at 12657.1,6802.5 h60
  text "9" at 9797.84,6682.5 h60
  text "Bottom Layer" at 10207.76,6682.5 h60
  text "Copper" at 11147.5,6682.5 h60
  text "1.40mil" at 12007.26,6682.5 h60
  text "10" at 9797.84,6562.5 h60
  text "Bottom Solder" at 10207.76,6562.5 h60
  text "Solder Resist" at 11147.5,6562.5 h60
  text "0.40mil" at 12007.26,6562.5 h60
  text "3.5" at 12657.1,6562.5 h60
  text "11" at 9797.84,6442.5 h60
  text "Bottom Overlay" at 10207.76,6442.5 h60
M13 Component Bodies Top:
  text ".Layer_Name" at 577,-858.49 h60
M14 Component Bodies Bottom:
  text ".Layer_Name" at 577,-858.49 h60
M15 Courtyards Top:
  text ".Layer_Name" at 577,-858.49 h60
M16 Courtyards Bottom:
  text ".Layer_Name" at 577,-858.49 h60
Drill Drawing:
  circle w10: c5363.72,2668.68 r27.63
  lines w10: 5336.09,2392.42 5391.34,2392.42 5391.34,2447.67 5336.09,2447.67 5336.09,2392.42 ; 5336.09,2516.74 5363.72,2530.55 5391.34,2516.74 5377.53,2544.36 5391.34,2571.99 5363.72,2558.18 5336.09,2571.99 5349.9,2544.36 5336.09,2516.74 ; 5336.09,2820.63 5391.34,2820.63 5363.72,2765.38 5336.09,2820.63 ; 5336.09,2903.51 5349.9,2903.51 5363.72,2889.7 5377.53,2903.51 5391.34,2903.51 5377.53,2917.32 5391.34,2931.14 5377.53,2931.14 5363.72,2944.95 5349.9,2931.14 5336.09,2931.14 5349.9,2917.32 5336.09,2903.51 ; 5336.09,3027.83 5349.9,3027.83 5349.9,3014.02 5377.53,3014.02 5377.53,3027.83 5391.34,3027.83 5391.34,3055.46 5377.53,3055.46 5377.53,3069.27 5349.9,3069.27 5349.9,3055.46 5336.09,3055.46 5336.09,3027.83 ; 5336.09,3138.34 5336.09,3152.15 5349.9,3165.96 5336.09,3179.78 5336.09,3193.59 5349.9,3193.59 5363.72,3179.78 5377.53,3193.59 5391.34,3193.59 5391.34,3179.78 5377.53,3165.96 5391.34,3152.15 5391.34,3138.34 5377.53,3138.34 5363.72,3152.15 5349.9,3138.34 5336.09,3138.34 ; 5336.09,3262.66 5391.34,3262.66 5391.34,3317.91 5336.09,3317.91 5336.09,3262.66 ; 5347.14,3273.71 5380.29,3273.71 5380.29,3306.86 5347.14,3306.86 5347.14,3273.71
  lines w12: 5286,2355.12 8517.49,2355.12 ; 5286,3349.68 8517.49,3349.68 ; 5623.86,2230.8 5623.86,3474 ; 5955.86,2230.8 5955.86,3474 ; 6592.43,2230.8 6592.43,3474 ; 6851.57,2230.8 6851.57,3474 ; 7226.72,2230.8 7226.72,3474 ; 7951.05,2230.8 7951.05,3474 ; 5286,2230.8 8517.49,2230.8 8517.49,3474 5286,3474 5286,2230.8
  text "Symbol" at 5360.59,3386.98 h72
  text "Quantity" at 5661.16,3386.98 h72
  text "Finished Hole Size" at 5993.16,3386.98 h72
  text "Plated" at 6629.72,3386.98 h72
  text "Hole Type" at 6888.86,3386.98 h72
  text "Drill Layer Pair" at 7264.02,3386.98 h72
  text "Hole Tolerance" at 7988.35,3386.98 h72
  text "47" at 5661.16,3262.66 h60
  text "7.87mil (0.200mm)" at 5993.16,3262.66 h60
  text "PTH" at 6629.72,3262.66 h60
  text "Round" at 6888.86,3262.66 h60
  text "Top Layer - Bottom Layer" at 7264.02,3262.66 h60
  text "6" at 5661.16,3138.34 h60
  text "10.00mil (0.254mm)" at 5993.16,3138.34 h60
  text "PTH" at 6629.72,3138.34 h60
  text "Round" at 6888.86,3138.34 h60
  text "Top Layer - Bottom Layer" at 7264.02,3138.34 h60
  text "171" at 5661.16,3014.02 h60
  text "16.00mil (0.406mm)" at 5993.16,3014.02 h60
  text "PTH" at 6629.72,3014.02 h60
  text "Round" at 6888.86,3014.02 h60
  text "Top Layer - Bottom Layer" at 7264.02,3014.02 h60
  text "4" at 5661.16,2889.7 h60
  text "35.43mil (0.900mm)" at 5993.16,2889.7 h60
  text "PTH" at 6629.72,2889.7 h60
  text "Round" at 6888.86,2889.7 h60
  text "Top Layer - Bottom Layer" at 7264.02,2889.7 h60
  text "22" at 5661.16,2765.38 h60
  text "40.00mil (1.016mm)" at 5993.16,2765.38 h60
  text "PTH" at 6629.72,2765.38 h60
  text "Round" at 6888.86,2765.38 h60
  text "Top Layer - Bottom Layer" at 7264.02,2765.38 h60
  text "24" at 5661.16,2641.06 h60
  text "43.31mil (1.100mm)" at 5993.16,2641.06 h60
  text "PTH" at 6629.72,2641.06 h60
  text "Round" at 6888.86,2641.06 h60
  text "Top Layer - Bottom Layer" at 7264.02,2641.06 h60
  text "8" at 5661.16,2516.74 h60
  text "45.28mil (1.150mm)" at 5993.16,2516.74 h60
  text "PTH" at 6629.72,2516.74 h60
  text "Round" at 6888.86,2516.74 h60
  text "Top Layer - Bottom Layer" at 7264.02,2516.74 h60
  text "4" at 5661.16,2392.42 h60
  text "125.98mil (3.200mm)" at 5993.16,2392.42 h60
  text "PTH" at 6629.72,2392.42 h60
  text "Round" at 6888.86,2392.42 h60
  text "Top Layer - Bottom Layer" at 7264.02,2392.42 h60
  text "286 Total" at 5661.16,2268.1 h60
  text "Drill tolerances:" at 5684.7,1572 h60
  text "For 7.874mil mil drill via +0/-7.874mil" at 5662.7,1438 h60
  text "For 10 mil drill via +0/-10 mil" at 5665,1300 h60
  text "For 16 mil drill via +0/-16 mil" at 5660,1180.28 h60
  text "For PTH +/- 3 mil" at 5655,1050 h60
  text "This not an impedance controlled board" at 5643,780 h60
  text "All Vias are non tented" at 5642,658 h60
  text ".Layer_Name" at 577,-858.49 h60
M17 Embedded Cavity:
  text ".Layer_Name" at 577,-858.49 h60
M18 Embedded Assembly:
  text ".Layer_Name" at 577,-858.49 h60
M19 Embedded Keepout:
  text ".Layer_Name" at 577,-858.49 h60

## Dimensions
4485,3050 to 4485,0 on M2 Board Dimensions
0,-400 to 1000,-400 on M2 Board Dimensions
0,0 to 0,3050 on M2 Board Dimensions
0,0 to 4485,0 on M2 Board Dimensions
